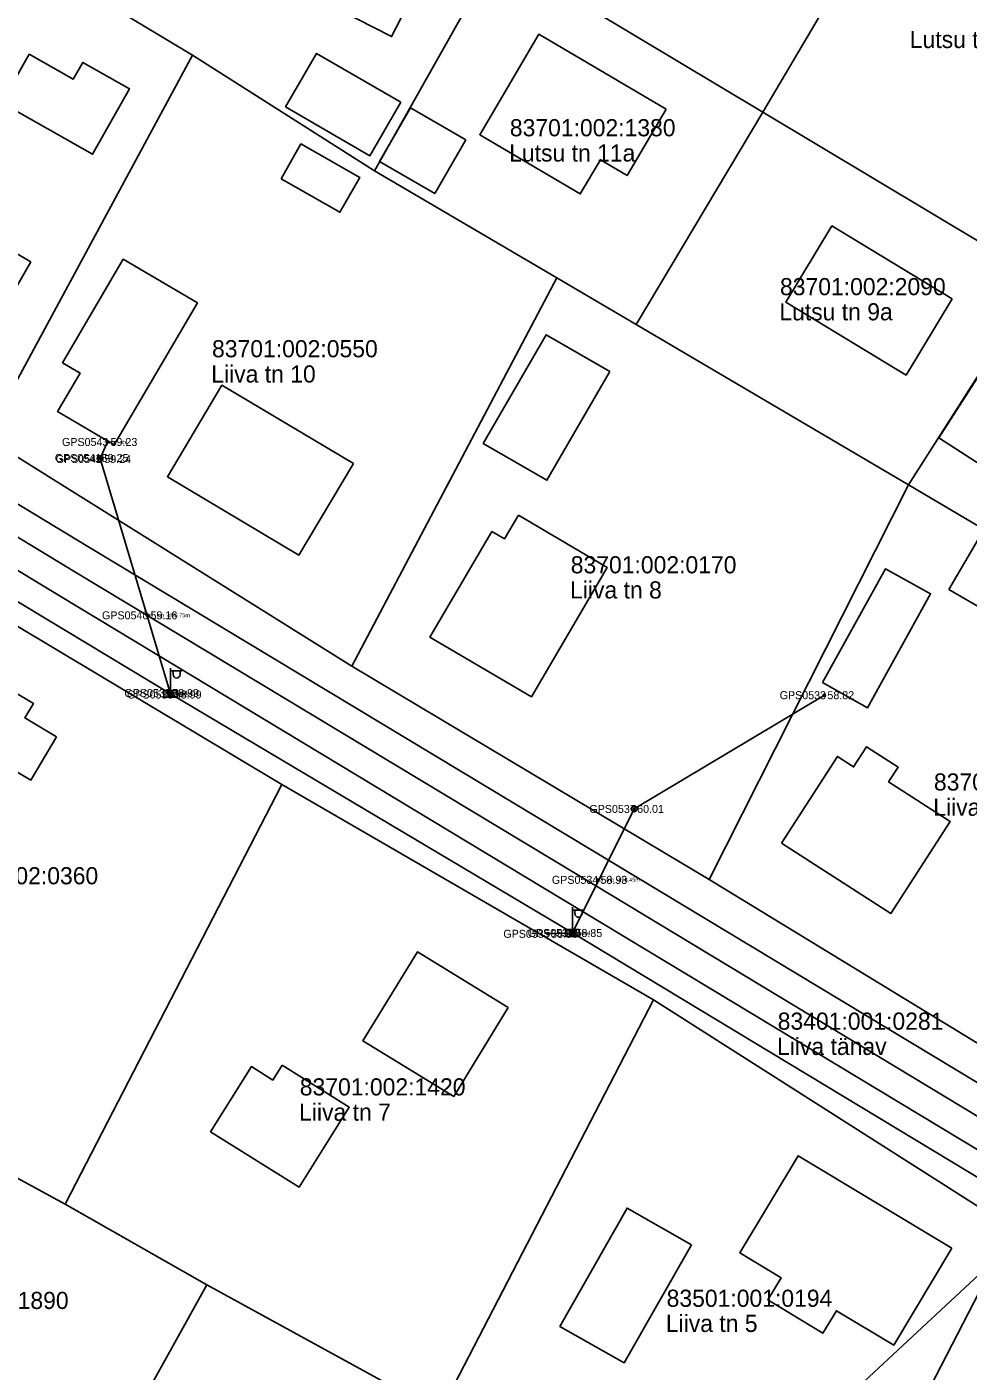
# Model space of a CAD drawing. Extents: x 580119 to 583377, y 6518915 to 6520820.
# Drawn here: x 581946.3 to 582028.7, y 6520100.4 to 6520218 of the extents above; entities that cross this region are included whole.
import ezdxf

# ---------------------------------------------------------------- set-up
doc = ezdxf.new("R2010")
doc.units = 0
for name, color, linetype in [('ELRAJATISMP', 7, 'Continuous'), ('Hoone Elu- või ühiskondlik hoone', 7, 'Continuous'), ('Hoone Kõrval- või tootmishoone', 7, 'Continuous'), ('L_AADRESS', 7, 'Continuous'), ('MAAMUDEL', 7, 'Continuous'), ('MOOTKORG-EH2000', 7, 'Continuous'), ('MOOTMPUNKT', 7, 'Continuous'), ('MOOTNR', 7, 'Continuous'), ('MPOHULIIN', 7, 'Continuous'), ('PIIR', 7, 'Continuous'), ('POST', 7, 'Continuous'), ('Rippe kõrgus', 7, 'Continuous'), ('Tee Liiklusala', 7, 'Continuous'), ('Tee Tänav Püsikate', 7, 'Continuous'), ('TUNNUS', 7, 'Continuous')]:
    doc.layers.add(name, color=color, linetype=linetype)

msp = doc.modelspace()

# ---------------------------------------------------------------- linework, layer by layer
at = {"layer": 'ELRAJATISMP'}
for p, q in [((581958.76, 6520159.96), (581958.76, 6520159.37)), ((581959.03, 6520159.96), (581959.03, 6520159.37)), ((581993.93, 6520139.04), (581993.93, 6520138.44)), ((581994.2, 6520139.04), (581994.2, 6520138.44))]:
    msp.add_line(p, q, dxfattribs=at)
for points in [[(581958.3, 6520159.96), (581959.49, 6520159.96), (581959.49, 6520159.37), (581958.3, 6520159.37)], [(581993.47, 6520139.04), (581994.66, 6520139.04), (581994.66, 6520138.44), (581993.47, 6520138.44)]]:
    msp.add_lwpolyline(points, close=True, dxfattribs=at)
at = {"layer": 'Hoone Elu- või ühiskondlik hoone'}
for points in [[(581969.13, 6520221.82), (581973.03, 6520229.42), (581982.14, 6520224.74), (581978.24, 6520217.15)], [(582002.26, 6520210.81), (581998.85, 6520205), (581996.51, 6520206.38), (581994.75, 6520203.39), (581985.96, 6520208.56), (581991.13, 6520217.35)], [(581946.68, 6520197.44), (581942.07, 6520189.42), (581934.99, 6520193.49), (581939.62, 6520201.52)], [(582027.3, 6520194.2), (582023.27, 6520187.54), (582012.73, 6520193.93), (582016.78, 6520200.59)], [(581974.91, 6520179.81), (581970.14, 6520171.8), (581958.62, 6520178.65), (581963.4, 6520186.66)], [(581989.34, 6520175.28), (581997.12, 6520170.71), (581990.48, 6520159.4), (581981.59, 6520164.62), (581987.02, 6520173.86), (581988.12, 6520173.21)], [(581948.92, 6520155.91), (581946.66, 6520152.11), (581943.85, 6520153.78), (581942.5, 6520151.5), (581933.76, 6520156.7), (581938.12, 6520164.04), (581946.9, 6520158.82), (581946.15, 6520157.56)], [(582012.37, 6520146.6), (582017.25, 6520154.19), (582018.67, 6520153.27), (582019.8, 6520155.02), (582022.56, 6520153.25), (582021.73, 6520151.96), (582027.11, 6520148.5), (582021.94, 6520140.45)], [(581988.45, 6520132.21), (581983.69, 6520124.44), (581975.74, 6520129.3), (581980.5, 6520137.08)], [(582027.28, 6520111.18), (582022.19, 6520102.68), (582017.17, 6520105.69), (582015.99, 6520103.74), (582011.17, 6520106.64), (582012.33, 6520108.58), (582008.73, 6520110.76), (582013.83, 6520119.25)]]:
    msp.add_lwpolyline(points, close=True, dxfattribs=at)
at = {"layer": 'Hoone Kõrval- või tootmishoone'}
for points in [[(581946.54, 6520215.6), (581950.38, 6520213.43), (581951.22, 6520214.89), (581955.32, 6520212.57), (581952.08, 6520206.86), (581944.14, 6520211.36)], [(581979.05, 6520211.41), (581976.34, 6520206.73), (581968.96, 6520211.01), (581971.68, 6520215.68)], [(581984.73, 6520208.12), (581982.02, 6520203.43), (581977.18, 6520206.24), (581979.89, 6520210.92)], [(581968.58, 6520204.72), (581970.31, 6520207.76), (581975.46, 6520204.84), (581973.72, 6520201.79)], [(581961.25, 6520193.87), (581953.97, 6520181.45), (581949.02, 6520184.36), (581950.98, 6520187.72), (581949.44, 6520188.62), (581954.76, 6520197.68)], [(581997.33, 6520187.86), (581991.83, 6520178.35), (581986.27, 6520181.56), (581991.77, 6520191.07)], [(582026.13, 6520182.05), (582031.31, 6520190.12), (582035.11, 6520187.68), (582029.93, 6520179.61)], [(582027.01, 6520168.8), (582029.59, 6520173.23), (582032.36, 6520171.62), (582029.78, 6520167.19)], [(582015.94, 6520160.64), (582021.46, 6520170.59), (582025.41, 6520168.41), (582019.89, 6520158.45)], [(581968.67, 6520127.18), (581974.54, 6520123.5), (581970.15, 6520116.5), (581962.41, 6520121.36), (581965.98, 6520127.06), (581967.85, 6520125.88)], [(582004.48, 6520111.47), (581998.58, 6520101.13), (581992.97, 6520104.33), (581998.85, 6520114.68)]]:
    msp.add_lwpolyline(points, close=True, dxfattribs=at)
at = {"layer": 'MOOTMPUNKT'}
for centre in [(581953.39, 6520181.69), (581952.62, 6520180.29), (581952.84, 6520180.2), (581956.89, 6520166.53), (581958.78, 6520159.73), (581959.01, 6520159.6), (582016.12, 6520159.54), (581999.47, 6520149.59), (581996.26, 6520143.39), (581991.94, 6520138.67), (581994.07, 6520138.74)]:
    msp.add_circle(centre, 0.1, dxfattribs=at)
at = {"layer": 'MPOHULIIN'}
msp.add_line((581994.07, 6520138.74), (581991.94, 6520138.67), dxfattribs=at)
for points in [[(582074.17, 6520090.2), (582035.13, 6520113.98), (581994.07, 6520138.74), (581958.9, 6520159.67), (581929.45, 6520177.38), (581899.05, 6520195.29), (581871.11, 6520211.35), (581850.55, 6520223.51), (581830.36, 6520235.9)], [(581953.39, 6520181.69), (581952.73, 6520180.24), (581958.9, 6520159.67)], [(582016.12, 6520159.54), (581999.47, 6520149.59), (581994.07, 6520138.74)], [(582035.13, 6520113.98), (582016.68, 6520096.8), (582017.06, 6520099.34)]]:
    msp.add_lwpolyline(points, dxfattribs=at)
at = {"layer": 'PIIR'}
for points in [[(582006.96, 6520249.43), (582026.75, 6520237.66), (582010.72, 6520210.54), (581991.78, 6520221.9)], [(582026.75, 6520237.66), (582046.99, 6520225.8), (582030.2, 6520198.89), (582010.72, 6520210.54)], [(581928.04, 6520234.91), (581954.1, 6520219.54), (581960.82, 6520215.52), (581942.75, 6520182.07), (581910.68, 6520201.36)], [(581987.39, 6520224.3), (581991.78, 6520221.9), (582010.72, 6520210.54), (581999.63, 6520191.97), (581992.7, 6520196.04), (581976.76, 6520205.4)], [(581960.82, 6520215.52), (581976.76, 6520205.4), (581992.7, 6520196.04), (581974.77, 6520162.07), (581942.75, 6520182.07)], [(582010.72, 6520210.54), (582030.2, 6520198.89), (582035.33, 6520196.52), (582023.47, 6520177.94), (581999.63, 6520191.97)], [(581992.7, 6520196.04), (581999.63, 6520191.97), (582023.47, 6520177.94), (582006.04, 6520143.43), (581974.77, 6520162.07)], [(582035.33, 6520196.52), (582041.21, 6520194.04), (582058.56, 6520184.01), (582047.13, 6520163.97), (582023.47, 6520177.94)], [(582023.47, 6520177.94), (582047.13, 6520163.97), (582055.76, 6520158.54), (582038.07, 6520123.88), (582006.04, 6520143.43)], [(581917.89, 6520132.56), (581922.47, 6520142.22), (581937.09, 6520170.6), (581968.64, 6520151.74), (581949.67, 6520115.03), (581931.46, 6520124.92)], [(581949.67, 6520115.03), (581968.64, 6520151.74), (582001.15, 6520132.88), (581982.47, 6520096.79), (581962.08, 6520107.97)], [(581982.47, 6520096.79), (582001.15, 6520132.88), (582032.54, 6520112.93), (582014.86, 6520078.65), (581991.36, 6520091.45)], [(581919.2, 6520103.01), (581920.52, 6520105.4), (581923.44, 6520110.63), (581926.36, 6520115.88), (581931.46, 6520124.92), (581949.67, 6520115.03), (581962.08, 6520107.97), (581949.99, 6520086.2), (581925.66, 6520099.62), (581923.71, 6520100.64)], [(582014.86, 6520078.65), (582032.54, 6520112.93), (582064.17, 6520093.83), (582047.03, 6520060.45), (582046.31, 6520060.89), (582020.31, 6520075.42)], [(581962.08, 6520107.97), (581982.47, 6520096.79), (581991.36, 6520091.45), (581978.94, 6520069.81), (581975.85, 6520071.52), (581949.99, 6520086.2)]]:
    msp.add_lwpolyline(points, close=True, dxfattribs=at)
msp.add_lwpolyline([(581942.75, 6520182.07), (581974.77, 6520162.07), (582006.04, 6520143.43), (582038.07, 6520123.88), (582050.1, 6520116.94), (582069.55, 6520104.59), (582123.3, 6520072.1), (582120.68, 6520059.28), (582096.36, 6520074.44), (582064.17, 6520093.83), (582032.54, 6520112.93), (582001.15, 6520132.88), (581968.64, 6520151.74), (581937.09, 6520170.6)], dxfattribs=at)
at = {"layer": 'POST'}
for p, q in [((581958.9, 6520159.92), (581958.9, 6520161.92)), ((581958.9, 6520161.67), (581959.9, 6520161.67)), ((581959.12, 6520161.35), (581959.12, 6520161.67)), ((581959.73, 6520161.35), (581959.73, 6520161.67)), ((581958.9, 6520159.67), (581958.9, 6520159.67)), ((581994.07, 6520138.99), (581994.07, 6520140.99)), ((581994.07, 6520140.74), (581995.07, 6520140.74)), ((581994.29, 6520140.42), (581994.29, 6520140.74)), ((581994.91, 6520140.42), (581994.91, 6520140.74)), ((581994.07, 6520138.74), (581994.07, 6520138.74))]:
    msp.add_line(p, q, dxfattribs=at)
for centre in [(581952.73, 6520180.24), (581958.9, 6520159.67), (581999.47, 6520149.59), (581994.07, 6520138.74)]:
    msp.add_circle(centre, 0.25, dxfattribs=at)
for centre in [(581959.43, 6520161.35), (581994.6, 6520140.42)]:
    msp.add_arc(centre, 0.306, 180, 0, dxfattribs=at)
at = {"layer": 'Tee Liiklusala'}
for points in [[(581909.94, 6520197.81), (581951.81, 6520172.47), (581995.76, 6520145.99), (582073.57, 6520099.11)], [(582070.63, 6520094.99), (581993.18, 6520141.71), (581949.23, 6520168.19), (581913.19, 6520190.06)]]:
    msp.add_lwpolyline(points, dxfattribs=at)
at = {"layer": 'Tee Tänav Püsikate'}
msp.add_lwpolyline([(581904.38, 6520197.95), (581914.45, 6520192.22), (581950.52, 6520170.33), (581994.47, 6520143.85), (582121.99, 6520066.88), (582130.06, 6520062.7)], dxfattribs=at)

# ---------------------------------------------------------------- texts
at = {"layer": 'L_AADRESS'}
for s, p in [('Lutsu tn 9', (582023.59, 6520216.15)), ('Lutsu tn 11a', (581988.53, 6520206.22)), ('Lutsu tn 9a', (582012.17, 6520192.33)), ('Liiva tn 10', (581962.46, 6520186.89)), ('Liiva tn 8', (581993.86, 6520168)), ('Liiva tn 6', (582025.64, 6520148.99)), ('Liiva tänav', (582011.97, 6520128.07)), ('Liiva tn 7', (581970.15, 6520122.32)), ('Liiva tn 5', (582002.24, 6520103.84))]:
    msp.add_text(s, height=1.5, dxfattribs=at).set_placement(p)
at = {"layer": 'MAAMUDEL'}
for s, p in [(' mp_ohl', (581953.39, 6520181.51)), (' kaabel', (581958.78, 6520159.56)), (' kaabel', (581959.01, 6520159.42)), (' kaabel', (581994.07, 6520138.57))]:
    msp.add_text(s, height=0.35, dxfattribs=at).set_placement(p)
at = {"layer": 'MOOTKORG-EH2000'}
for s, p in [(' 59.23', (581953.39, 6520181.34)), (' 59.25', (581952.62, 6520179.94)), (' 59.24', (581952.84, 6520179.85)), (' 59.16', (581956.89, 6520166.18)), (' 58.99', (581958.78, 6520159.38)), (' 58.99', (581959.01, 6520159.25)), (' 58.82', (582016.12, 6520159.19)), (' 60.01', (581999.47, 6520149.24)), (' 58.93', (581996.26, 6520143.04)), (' 58.90', (581991.94, 6520138.32)), (' 58.85', (581994.07, 6520138.39))]:
    msp.add_text(s, height=0.7, dxfattribs=at).set_placement(p)
at = {"layer": 'MOOTNR'}
for s, p in [('GPS0543 ', (581949.4, 6520181.34)), ('GPS0541 ', (581948.77, 6520179.94)), ('GPS0542 ', (581948.85, 6520179.85)), ('GPS0540 ', (581952.9, 6520166.18)), ('GPS0539 ', (581954.86, 6520159.38)), ('GPS0538 ', (581955.09, 6520159.25)), ('GPS0533 ', (582012.2, 6520159.19)), ('GPS0537 ', (581995.55, 6520149.24)), ('GPS0534 ', (581992.27, 6520143.04)), ('GPS0535 ', (581988.02, 6520138.32)), ('GPS0536 ', (581990.15, 6520138.39))]:
    msp.add_text(s, height=0.7, dxfattribs=at).set_placement(p)
at = {"layer": 'Rippe kõrgus'}
for s, p in [(' el_mp_ohl6.75m', (581956.89, 6520166.36)), (' el_mp_ohl8.45m', (581996.26, 6520143.22))]:
    msp.add_text(s, height=0.35, dxfattribs=at).set_placement(p)
at = {"layer": 'TUNNUS'}
for s, p in [('83701:002:1380', (581988.59, 6520208.43)), ('83701:002:2090', (582012.23, 6520194.53)), ('83701:002:0550', (581962.53, 6520189.1)), ('83701:002:0170', (581993.92, 6520170.2)), ('83701:002:0330', (582025.7, 6520151.2)), ('83701:002:0360', (581938.07, 6520143)), ('83401:001:0281', (582012.03, 6520130.28)), ('83701:002:1420', (581970.21, 6520124.53)), ('83701:002:1890', (581935.48, 6520105.85)), ('83501:001:0194', (582002.31, 6520106.04))]:
    msp.add_text(s, height=1.5, dxfattribs=at).set_placement(p)

doc.saveas('drawing.dxf')
